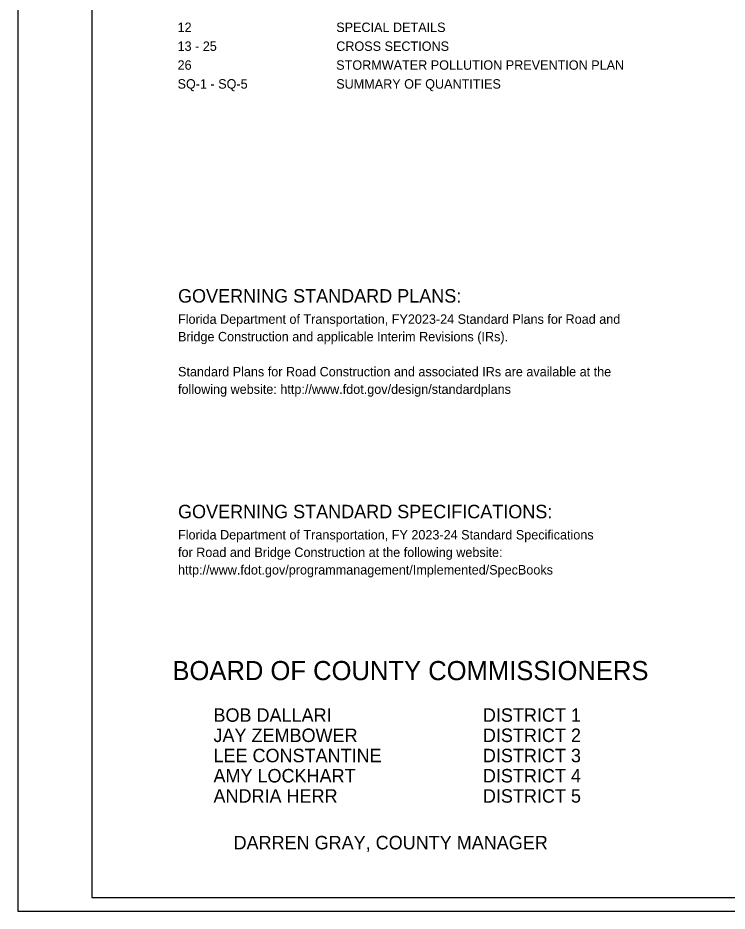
# Model space of a CAD drawing. Extents: x 2157516 to 2331756, y 2153820 to 2265756.
# Drawn here: x 2157516 to 2213121, y 2153820 to 2223812 of the extents above; entities that cross this region are included whole.
import ezdxf

# ---------------------------------------------------------------- set-up
doc = ezdxf.new("R2010")
doc.units = 0
for name, color, linetype in [('Default', 7, 'Continuous'), ('PlotBorder_dp', 7, 'Continuous'), ('SheetBorder_dp', 7, 'Continuous'), ('TextLabel', 7, 'Continuous'), ('TextNotes', 7, 'Continuous')]:
    doc.layers.add(name, color=color, linetype=linetype)

msp = doc.modelspace()

# ---------------------------------------------------------------- linework, layer by layer
at = {"layer": 'PlotBorder_dp'}
msp.add_lwpolyline([(2157516, 2153820), (2331756, 2153820), (2331756, 2265756), (2157516, 2265756)], close=True, dxfattribs=at)
at = {"layer": 'SheetBorder_dp'}
for p, q in [((2163324, 2264700), (2163324, 2154876)), ((2163324, 2154876), (2325948, 2154876))]:
    msp.add_line(p, q, dxfattribs=at)

# ---------------------------------------------------------------- texts
at = {"layer": 'Default'}
msp.add_text('BOARD OF COUNTY COMMISSIONERS', height=1499.54, dxfattribs=at).set_placement((2169632, 2171919))
at = {"layer": 'TextLabel'}
for s, p in [('GOVERNING STANDARD PLANS:', (2170072, 2201501)), ('GOVERNING STANDARD SPECIFICATIONS:', (2170072, 2184602)), ('BOB DALLARI', (2172852, 2168654)), ('DISTRICT 1', (2193972, 2168654)), ('JAY ZEMBOWER', (2172852, 2167070)), ('DISTRICT 2', (2193972, 2167070)), ('LEE CONSTANTINE', (2172852, 2165486)), ('DISTRICT 3', (2193972, 2165486)), ('AMY LOCKHART ', (2172852, 2163902)), ('DISTRICT 4', (2193972, 2163902)), ('ANDRIA HERR', (2172852, 2162318)), ('DISTRICT 5 ', (2193972, 2162318)), ('DARREN GRAY, COUNTY MANAGER', (2174426, 2158660))]:
    msp.add_text(s, height=1056, dxfattribs=at).set_placement(p)
at = {"layer": 'TextNotes'}
for s, p in [('12 ', (2170036, 2222703)), ('SPECIAL DETAILS', (2182475, 2222703)), ('13 - 25', (2170036, 2221224)), ('CROSS SECTIONS', (2182475, 2221224)), ('26', (2170036, 2219746)), ('STORMWATER POLLUTION PREVENTION PLAN', (2182475, 2219746)), ('SQ-1 - SQ-5', (2170036, 2218268)), ('SUMMARY OF QUANTITIES ', (2182475, 2218268)), ('Florida Department of Transportation, FY2023-24 Standard Plans for Road and', (2170072, 2199839)), ('Bridge Construction and applicable Interim Revisions (IRs).', (2170072, 2198466)), ('Standard Plans for Road Construction and associated IRs are available at the', (2170072, 2195720)), ('following website: http://www.fdot.gov/design/standardplans', (2170072, 2194348)), ('Florida Department of Transportation, FY 2023-24 Standard Specifications', (2170072, 2182941)), ('for Road and Bridge Construction at the following website:', (2170072, 2181568)), ('http://www.fdot.gov/programmanagement/Implemented/SpecBooks', (2170072, 2180195))]:
    msp.add_text(s, height=739.2, dxfattribs=at).set_placement(p)

doc.saveas('drawing.dxf')
